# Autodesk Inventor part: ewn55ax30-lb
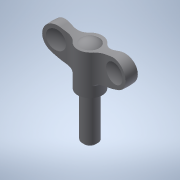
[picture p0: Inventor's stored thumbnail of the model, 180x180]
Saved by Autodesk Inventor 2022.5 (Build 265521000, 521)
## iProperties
Created: 2016-12
Part Number: ewn55ax30-lb
Material: 一般
Document SubType Name: Modeling
Designer: imaocorp
Density: 1 g/cm^3
Appearance: 既定
Author: imaocorp
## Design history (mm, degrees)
node "ewn55ax30-lb.x_t1"
node "ewn55ax30-lb"
node "Base1"
